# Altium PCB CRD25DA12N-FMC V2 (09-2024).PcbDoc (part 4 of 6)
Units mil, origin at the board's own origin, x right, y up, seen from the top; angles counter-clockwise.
Board outline 8000 x 8000 mil, 6 copper layers (Top Layer, Layer 2, Layer 3, Layer 4, Layer 5, Bottom Layer), stack 91 mil thick; 602 components, 333 nets, 1670 pads, 639 vias.
Unrouted connection lines stored in the file: 1.
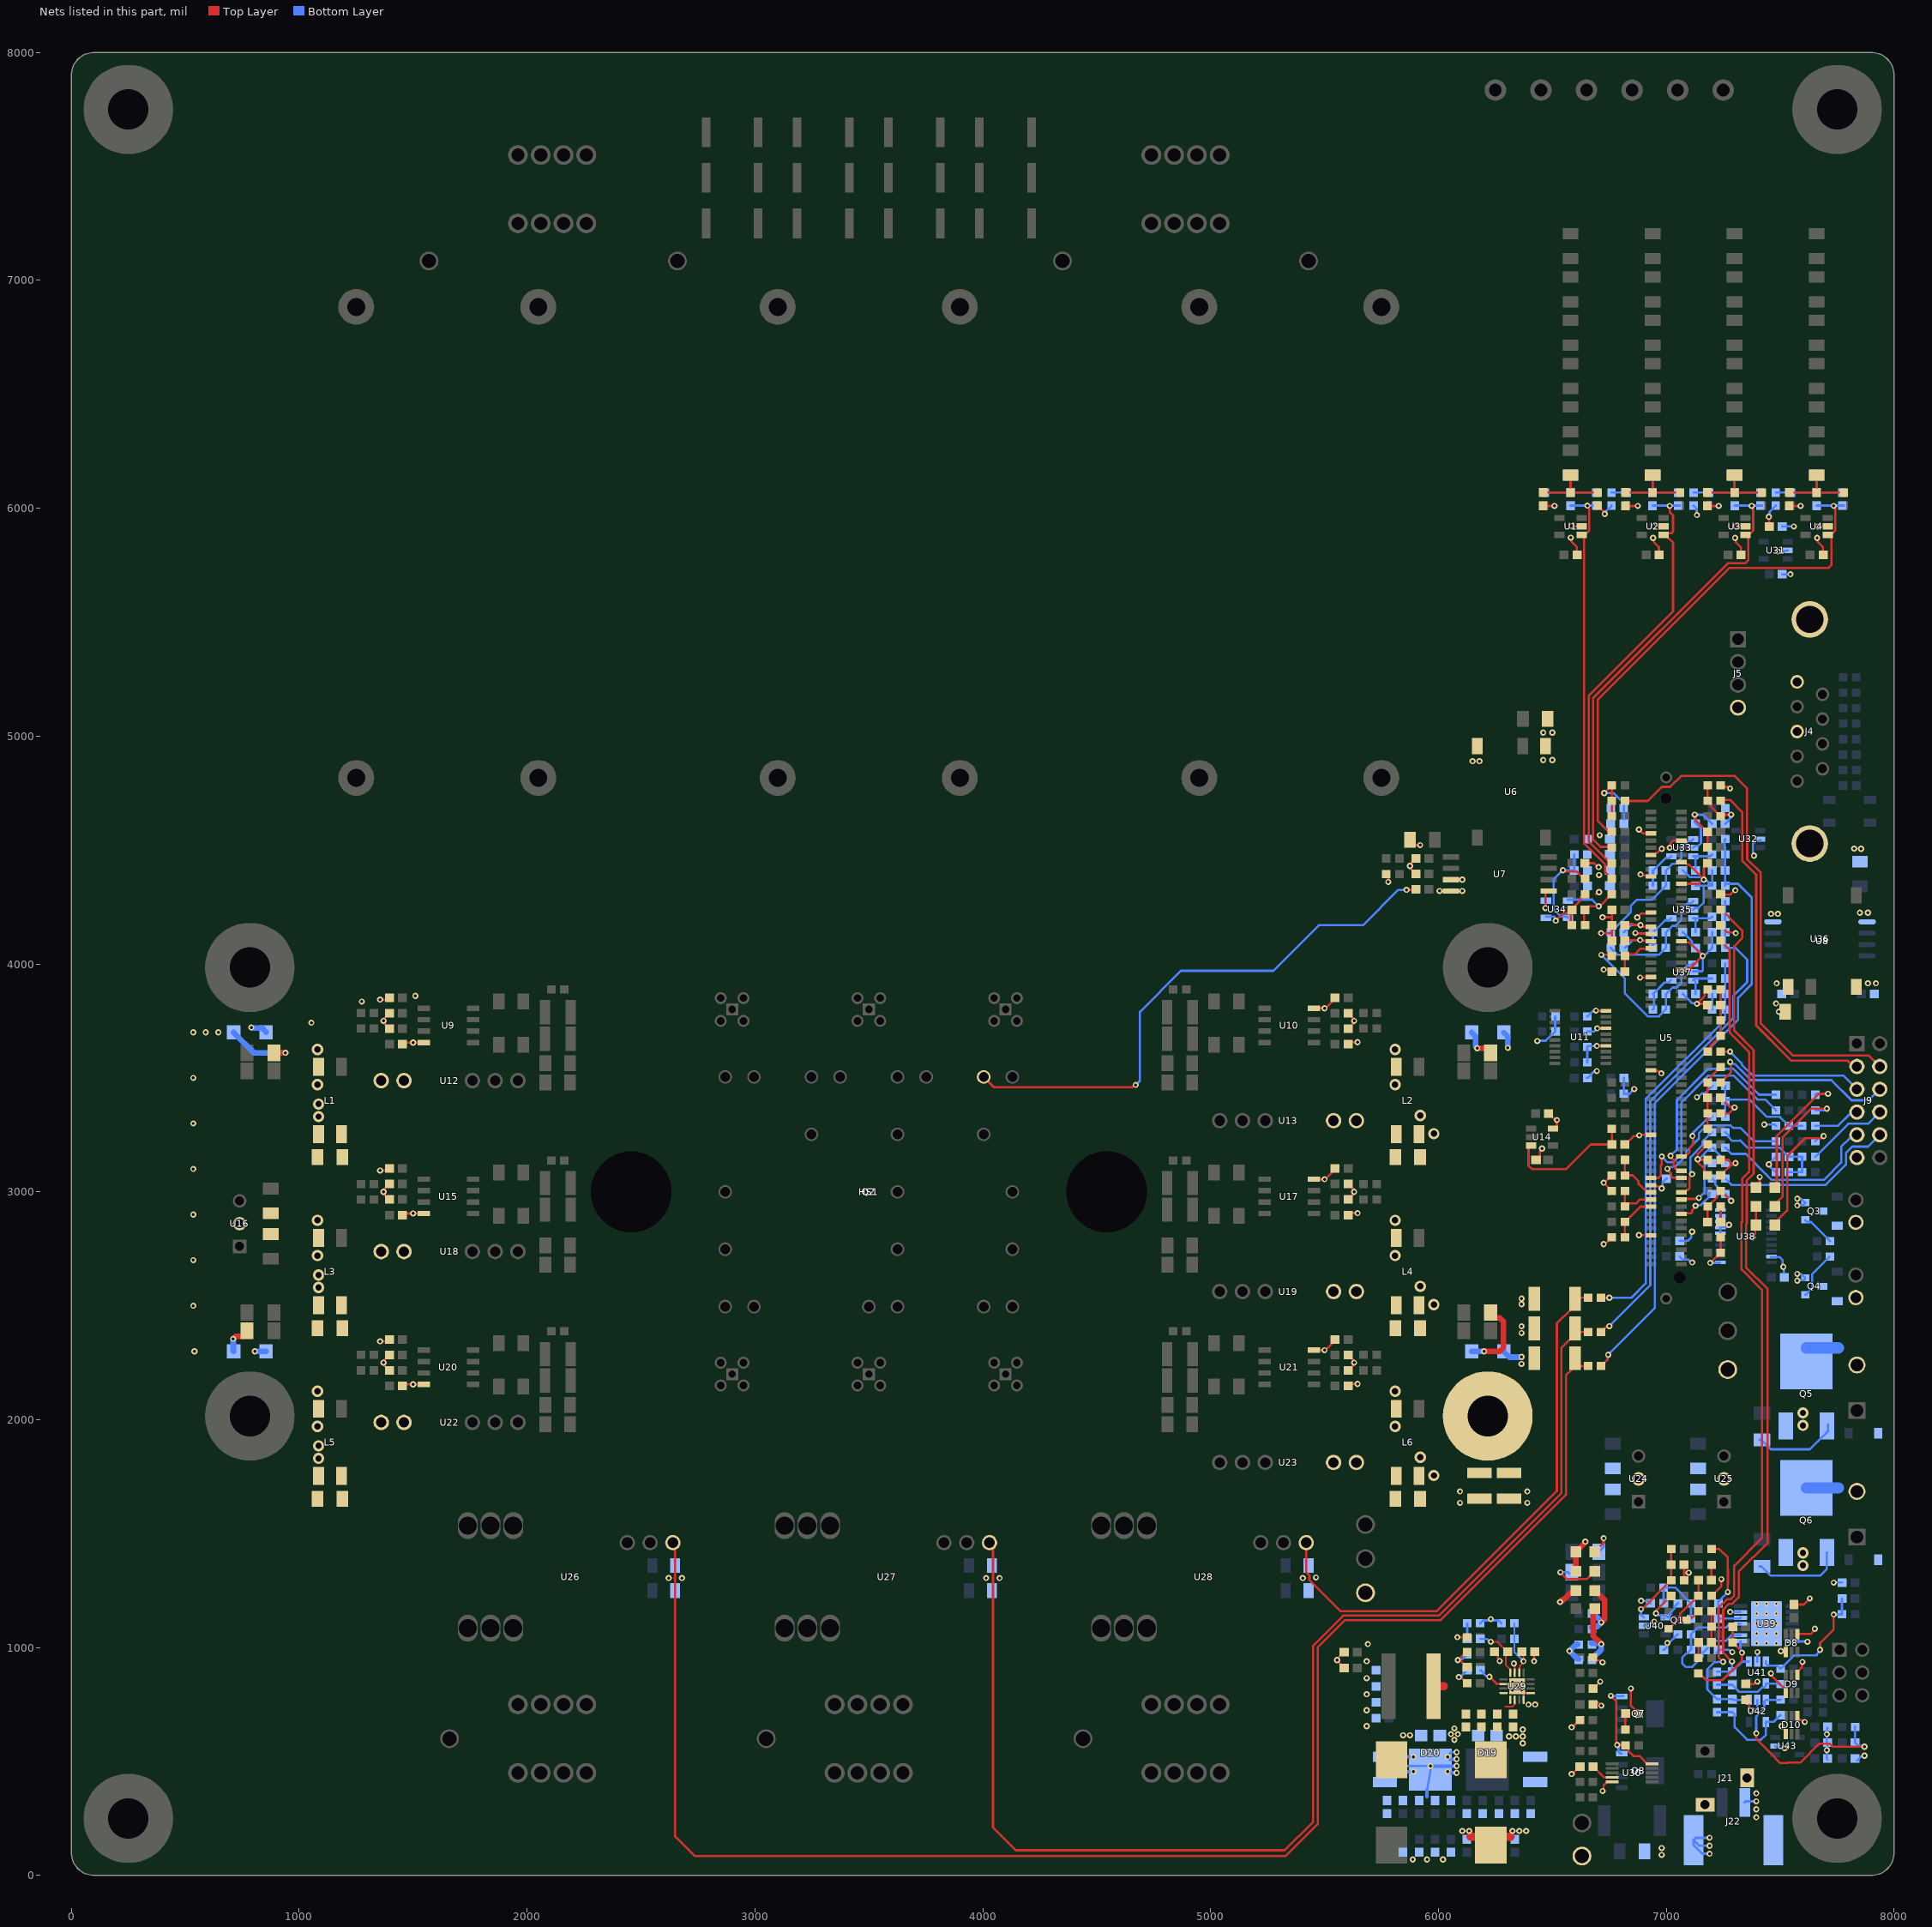
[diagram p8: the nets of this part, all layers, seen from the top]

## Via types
v1: diameter 27, hole 13, Top Layer to Bottom Layer, tented both sides, 543 vias
v2: diameter 50, hole 28, Top Layer to Bottom Layer, tented both sides, 76 vias
v3: diameter 19.68, hole 7.87, Top Layer to Bottom Layer, tented top, 15 vias
v4: diameter 19.68, hole 7.87, Top Layer to Bottom Layer, tented both sides, 5 vias

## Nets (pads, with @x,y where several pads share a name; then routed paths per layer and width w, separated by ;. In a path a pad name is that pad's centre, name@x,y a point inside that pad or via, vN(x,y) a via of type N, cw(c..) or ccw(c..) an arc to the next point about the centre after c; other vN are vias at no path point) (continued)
GND: C1.2 C2.2 C3.2 C4.2 C5.2 C6.2 C7.2 C8.2 C9.2 C10.2 C11.2 C13.2 C15.2 C16.2 C19.2 C21.2 C22.2 C23.2 C24.2 C25.2 C26.2 C27.2 C30.2 C31.2 C32.2 C33.2 C34.2 C35.2 C38.2 C39.2 C44.2 C45.2 C46.2 C49.2 C50.2 C53.2 C54.2 C55.2 C56.2 C57.2 C58.2 C61.2 C62.2 C63.2 C64.2 C71.2 C72.2 C75.2 C76.2 C77.2 C78.2 C81.2 C82.2 C89.2 C92.2 C95.2 C96.2 C97.2 C99.2 C100.2 C101.2 C102.2 C103.2 C104.2 C109.2 C117.2 C118.2 C122.2 C123.2 C124.2 C125.2 C126.2 C127.2 C129.2 C130.2 C131.2 C133.1 C134.2 C135.2 C136.2 C137.2 C138.2 C140.2 C142.2 C143.2 C144.2 C146.2 C147.2 C148.2 C149.2 C150.2 C151.2 C152.2 C153.2 C154.2 C155.2 C156.2 C157.2 C158.2 C159.2 C160.2 C161.2 C162.1 C163.1 C164.1 C166.2 C169.2 C170.2 C171.2 C172.2 C175.2 C178.2 C179.2 C180.2 C182.2 C183.2 C184.2 C186.2 C187.2 C188.2 C189.2 C190.2 C191.2 C192.2 C193.2 C194.2 C195.2 C196.2 C197.2 C198.2 C199.2 C200.2 C201.2 C202.2 C203.2 D1.1 D2.1 D3.1 D4.1 D5.1 D6.1 D8.1 D8.4 D9.1 D9.4 D10.1 D10.4 D11.1 D12.1 D15.1 D16.1 D20.1 J9.11 J21.2 J21.3 J22.1 J22.3 J22.4 L1.2 L2.2 L3.2 L4.2 L5.2 L6.2 L9.1 Q3.2 Q4.2 Q5.3 Q6.3 R38.1 R46.1 R66.1 R87.1 R91.2 R93.1 R96.1 R101.1 R108.1 R110.1 R111.1 R112.1 R113.1 R117.1 R125.1 R133.1 R134.1 R138.1 R139.1 R142.1 R145.1 R149.1 R150.1 R183.1 R186.1 R189.1 R198.1 R201.2 R202.1 R207.1 R212.1 R214.1 R215.1 R216.1 R217.1 R218.1 R219.1 R220.1 R228.1 R236.1 R254.1 R255.1 R258.1 R260.1 R263.1 TP7.1 TP10.1 TP15.1 U1.2 U2.2 U3.2 U4.2 U5.7 U5.10 U5.13 U5.16 U5.19 U5.22 U5.29 U5.35 U5.38 U5.46 U5.47 U5.65 U5.83 U5.97 U5.111 U6.1 U7.5 U8.1 U9.4 U10.4 U11.4 U11.7 U11.10 U14.5 U15.4 U16.2 U17.4 U20.4 U21.4 U24.2 U25.2 U29.1 U29.7 U29.16 U29.17 U30.5 U31.2 U32.2 U33.2 U34.5 U35.2 U36.4 U37.2 U38.1 U38.6 U38.7 U38.8 U38.9 U38.10 U38.19 U39.6 U39.14 U39.15 U40.2 U41.2 U42.2 U43.2 | length 13145.5
  Top Layer w8: v1(6331.08,930) 6331.08,924.86 6335.16,920.78 6335.16,889.81 U29.7@6334.87,889.52 ; v1(6720.98,370.5) 6724.62,374.14 6724.62,394.48 U30.5@6739.86,409.72 ; U30.5@6740.77,410.63 U30.5@6762.91,410.63
  Top Layer w10: v1(1355,2343.5) 1382.92,2343.5 C71.2@1391.42,2352 ; v1(1355,3093.5) 1382.92,3093.5 C49.2@1391.42,3102 ; v1(1355,3843.5) 1382.92,3843.5 C26.2@1391.42,3852 ; C77.2@1391.42,2216 1391.42,2220.05 1373.25,2238.22 1373.25,2246.75 v1(1370,2250) 1373.25,2253.25 1373.25,2261.78 1391.42,2279.95 C75.2@1391.42,2284 ; C57.2@1391.42,2966 1391.42,2970.05 1373.25,2988.22 1373.25,2996.75 v1(1370,3000) 1373.25,3003.25 1373.25,3011.78 1391.42,3029.95 C54.2@1391.42,3034 ; C34.2@1391.42,3716 1391.42,3720.05 1373.25,3738.22 1373.25,3746.75 v1(1370,3750) 1373.25,3753.25 1373.25,3761.78 1391.42,3779.95 C32.2@1391.42,3784 ; C81.2@1448.58,2148 1455.58,2155 v1(1500,2155) U20.4@1546.73,2155 ; C61.2@1448.58,2898 1455.58,2905 v1(1500,2905) U15.4@1546.73,2905 ; C38.2@1448.58,3648 1455.58,3655 v1(1500,3655) U9.4@1546.73,3655 ; U21.4@5453.27,2305 v1(5500,2305) 5505,2305 5505,2306.53 5550.47,2352 C72.2@5551.42,2352 ; U17.4@5453.27,3055 v1(5500,3055) 5505,3055 5505,3056.53 5550.47,3102 C50.2@5551.42,3102 ; U10.4@5453.27,3805 v1(5500,3805) 5505,3805 5505,3806.53 5550.47,3852 C27.2@5551.42,3852 ; C99.2@5586.42,900 5586.42,912.05 5555,943.47 5555,949.53 5575.47,970 C97.2@5586.42,970 ; C82.2@5608.58,2148 5617.08,2156.5 v1(5645,2156.5) ; C78.2@5608.58,2216 5608.58,2220.05 5626.75,2238.22 5626.75,2246.75 v1(5630,2250) 5626.75,2253.25 5626.75,2261.78 5608.58,2279.95 C76.2@5608.58,2284 ; C62.2@5608.58,2898 5617.08,2906.5 v1(5645,2906.5) ; C58.2@5608.58,2966 5608.58,2970.05 5626.75,2988.22 5626.75,2996.75 v1(5630,3000) 5626.75,3003.25 5626.75,3011.78 5608.58,3029.95 C55.2@5608.58,3034 ; C39.2@5608.58,3648 5617.08,3656.5 v1(5645,3656.5) ; C35.2@5608.58,3716 5608.58,3720.05 5626.75,3738.22 5626.75,3746.75 v1(5630,3750) 5626.75,3753.25 5626.75,3761.78 5608.58,3779.95 C33.2@5608.58,3784 ; v1(6083.11,1045) R142.1@6126.38,1045 ; v1@6102.73,866.75 6125.47,844 R149.1@6126.38,844 ; v1(6135,195) 6135,175.86 6140.86,170 ; L9.1@6192.99,170 L9.1@6230,132.99 L9.1@6267.01,170 ; C95.2@6246.42,981 6247.37,981 6261.24,967.14 6261.24,952.5 6268.91,944.82 v1(6268.91,940.28) ; 6317.98,170 6323.84,175.86 6323.84,193.84 v1(6325,195) ; v1(6331.08,930) 6334.33,926.75 6334.33,921.07 v1@6334.87,920.53 ; v4(6365,810) U29.17@6374.53,800.47 ; U29.16@6374.53,770.77 U29.17@6374.53,800.47 ; U29.1@6404.23,800.47 U29.17@6374.53,800.47 ; v1(6420,940) 6420,977.42 C96.2@6423.58,981 ; R91.2@6428.38,3140 6431.29,3140 6445.16,3153.86 6445.16,3175.56 6455,3185.4 v1(6455,3190) ; C1.2@6460,6011.42 6461.42,6010 v1(6509.46,6010) ; v1(6470,4245) 6470,4313.19 6476.81,4320 6488.54,4320 U7.5@6495.35,4313.19 ; C45.2@6483.58,3344 6484.53,3344 6510.27,3318.25 6516.75,3318.25 v1(6520,3315) 6520,3288.18 6511.22,3279.4 U14.5@6503.23,3279.4 ; v1(6580.67,5871.13) 6583.92,5867.88 6583.92,5853.71 6607.63,5830 6607.63,5795.95 C6.2@6608.58,5795 ; v1(6583.58,5921.42) 6584.29,5920.71 6627.52,5920.71 U1.2@6628.23,5920 ; v1(6585,445) 6587.47,445 6620.47,478 C109.2@6621.42,478 ; v1(6585,650) 6588.47,650 6618.47,680 R150.1@6625,680 ; C15.2@6638.58,4442 6683.4,4442 6700.4,4425 v1(6703.02,4425) ; C103.2@6678.58,750 6685.82,757.24 6700.74,757.24 ; C101.2@6678.58,819 6679.53,819 6710,849.47 v1(6710,850) ; R145.1@6678.62,956 6691.58,943.04 6707.36,943.04 6715.4,935 v1(6720,935) ; 6691.4,4306 6700.4,4315 v1(6705,4315) ; v1(6691.5,3795) 6691.93,3794.57 6734.57,3794.57 U11.10@6735,3794.13 ; v1(6695,3640) 6695.3,3640.3 6734.7,3640.3 U11.4@6735,3640.59 ; v1(6697.19,3717.36) U11.7@6735,3717.36 ; R38.1@6700,6011.38 6700,6010.47 v1@6726.75,5983.73 ; 6701.75,758.25 v1(6715,745) ; v1(6714.02,4135) 6761.42,4135 ; v1(6720,4205) 6761.42,4205 ; v1(6725,2770) 6728.25,2773.25 6733.73,2773.25 6760.47,2800 R110.1@6761.38,2800 ; v1(6725,3975) 6760.42,3975 C25.2@6761.42,3974 ; U30.5@6739.86,409.72 U30.5@6740.77,410.63 ; R101.1@6761.38,3004 6760.47,3004 6725,3039.47 v1(6725,3040) 6728.47,3040 6760.47,3072 R96.1@6761.38,3072 ; C24.2@6761.42,4110 6761.42,4135 ; C21.2@6761.42,4240 C21.2@6761.42,4238 6761.42,4205 ; C46.2@6818.58,3208 6819.53,3208 6855.79,3244.26 6878.25,3244.26 v1(6881.5,3247.52) 6883.89,3249.9 6932.97,3249.9 U5.83@6933.07,3249.8 ; C2.2@6820,6011.42 6821.42,6010 v1(6875,6010) ; v1(6845,820) 6845,743.58 6863.76,724.81 6863.76,723.86 6877.63,710 C104.2@6878.58,710 ; v1(6864.55,4135.68) 6866.54,4133.69 6931.08,4133.69 U5.35@6933.07,4131.69 ; v1(6872.9,4204.39) 6874,4204.39 6890.94,4221.34 6928.23,4221.34 U5.29@6933.07,4226.18 ; v1(6880,2810) 6880.57,2809.43 6929.43,2809.43 U5.111@6930,2810 ; v1(6880,4590) 6897.36,4572.64 U5.7@6933.07,4572.64 ; v1(6885,3940) 6885.47,3940.47 6934.53,3940.47 U5.47@6935,3940.94 ; v1(6887.16,4392.84) 6891.76,4392.84 6896.1,4388.5 6928.23,4388.5 U5.19@6933.07,4383.66 ; U5.13@6914.65,4482.8 6951.5,4482.8 6957.5,4488.8 6961.25,4488.8 6977.45,4505 v1(6980.19,4505) ; U5.97@6928.23,3034.17 U5.97@6933.07,3029.33 6937.91,3024.49 6965.91,3024.49 6975.4,3015 v1(6980,3015) ; U5.65@6935,3531.5 6936.04,3530.46 6964.94,3530.46 6975.4,3520 v1(6978.82,3520) ; v1(6942.09,5869.71) 6945.34,5866.45 6945.34,5852.28 6967.63,5830 6967.63,5795.95 C7.2@6968.58,5795 ; v1(6945,5920) U2.2@6988.23,5920 ; v1(7015,4510) 7018.25,4513.25 7018.25,4528.25 7031.14,4541.14 U5.10@7066.93,4541.14 ; U5.46@7066.93,3974.21 7071.77,3979.06 7104.06,3979.06 v1(7160,4035) 7099.65,4095.35 7071.77,4095.35 U5.38@7066.93,4100.2 ; U5.22@7066.93,4352.17 7142.57,4352.17 7160.4,4370 v1(7165,4370) ; U5.16@7071.77,4451.5 U5.16@7066.93,4446.65 7080.71,4446.65 7091.36,4436 7099,4436 v1(7165,4370) ; R138.1@7078.62,1295 R138.1@7078.62,1295 7078.58,1330 ; C89.2@7078.58,1363 7078.58,1330 ; C89.2@7079.53,1347.25 C89.2@7079.53,1363 ; v1(7098.39,1328.39) 7080.19,1328.39 cw(c7080.19,1330) 7078.58,1330 ; v1(7125,4655) 7128.25,4651.75 7128.25,4632.22 7180.47,4580 C11.2@7181.42,4580 C13.2@7181.42,4511 ; C3.2@7180,6011.42 7181.42,6010 v1(7230,6010) ; C30.2@7181.42,3820 7176.42,3825 v1(7135,3825) 7167.52,3857.52 7167.52,3875.04 7180.47,3888 R66.1@7181.38,3888 ; C16.2@7181.42,4442 7180.47,4442 7166.61,4428.14 7166.61,4427.19 7165,4425.58 v1(7165,4370) ; v1(7193.1,2688.1) 7193.82,2688.1 7237.72,2732 R112.1@7238.62,2732 R111.1@7238.62,2800 ; R139.1@7198.62,1227 7199.53,1227 7241.89,1269.36 v1(7241.89,1300) ; C63.2@7238.58,2868 C63.2@7238.58,2868 R108.1@7238.62,2936 ; C53.2@7238.58,3072 7239.53,3072 7253.39,3085.86 7253.39,3086.71 7284.8,3118.12 7296.33,3118.12 v1(7304.07,3125.86) ; R93.1@7238.62,3140 7270.98,3140 7292.87,3118.12 ; R87.1@7238.62,3344 7274,3344 v1(7300,3370) 7296.75,3373.25 7278.27,3373.25 7239.53,3412 C44.2@7238.58,3412 ; C23.2@7238.58,4168 7239.53,4168 7269.27,4138.25 7301.75,4138.25 v1(7305,4135) ; C19.2@7238.58,4304 7281.99,4304 7301.26,4323.27 v1(7303.03,4323.27) ; R46.1@7238.62,4790 7251.58,4777.04 7268.36,4777.04 7275.4,4770 v1(7280,4770) ; C63.2@7239.6,2869.02 7239.6,2868.79 7253.39,2855 v1(7275.54,2855) ; v1(7302.09,5869.71) 7305.34,5866.45 7305.34,5852.28 7327.63,5830 7327.63,5795.95 C8.2@7328.58,5795 ; v1(7305,5920) U3.2@7348.23,5920 ; C102.2@7348.58,771 7349.53,771 7363.39,757.14 7363.39,735.07 7370,728.46 v1(7370,723.86) ; C100.2@7348.58,840 7385.52,840 7395.52,850 v1(7400.12,850) ; v1(7378.5,2800) 7378.5,2803.88 7390,2815.38 7390,2850.34 D3.1@7393.66,2854 D2.1@7393.66,2936 ; D1.1@7387.66,3012 7410,3034.34 v1(7410,3065) ; v1(7450,5962.36) 7451.14,5961.23 C5.2@7451.14,5920 ; v1(7459.15,886.52) 7462.41,883.26 7462.41,876.41 7524.41,814.41 D9.1@7524.41,800.63 ; v1(7502.68,984.44) 7520.6,984.44 D8.1@7524.41,980.63 ; v1(7506,655.26) 7506,652.82 7520.55,638.27 D10.1@7520.55,625 ; C4.2@7540,6011.42 7541.42,6010 v1(7589.46,6010) ; C92.2@7560,1188.58 7603.58,1188.58 v1(7630,1215) ; D10.4@7575.59,699.37 7575.59,685.59 7579.45,681.73 7594.67,681.73 7603.29,673.11 v1(7607.89,673.11) ; D9.4@7575.59,879.37 7575.59,893.15 7594.61,912.17 7594.61,933.41 v1(7597.86,936.66) ; D8.4@7575.59,1059.37 7633.25,1059.37 7652.35,1078.46 v1(7652.35,1082.35) ; v1(7662.09,5869.71) 7665.34,5866.45 7665.34,5852.28 7687.63,5830 7687.63,5795.95 C9.2@7688.58,5795 ; v1(7665,5920) U4.2@7708.23,5920 ; 6761.42,4135 C22.2@6761.42,4170 6761.42,4205
  Top Layer w25: v1(6534.01,1199.85) 6534.55,1199.85 6542,1207.3 6547.3,1207.3 6578.88,1238.88 6592.54,1238.88 D6.1@6603.66,1250 ; D5.1@6603.66,1335 D4.1@6603.66,1420 6644.62,1460.96 6644.62,1464.62 v1(6645,1465)
  Top Layer w35: 6140.86,170 L9.1@6192.99,170 ; L9.1@6267.01,170 6317.98,170
  Bottom Layer w10: 5860,480 v1(5965,480) ; D20.1@5950,376.14 D20.1@5965,464.06 ; v1(6040,455) D20.1@6045,450 ; D20.1@6050,510 v1(6040,520) 6040,525.51 6054.49,540 v1(6080,540) ; v1(6090,870) 6093.25,873.25 6098.73,873.25 6125.47,900 C171.2@6126.42,900 ; R255.1@6183.62,1106 6196.58,1118.96 6219.36,1118.96 6225.4,1125 6234.6,1125 6240.64,1118.96 6263.42,1118.96 R254.1@6276.38,1106 ; D15.1@6287.4,2298.03 D15.1@6287.4,2300 ; D11.1@6287.4,3698.03 D11.1@6287.4,3700 ; D15.1@6311.93,2273.5 D15.1@6313.9,2273.5 ; v1(6433.85,3661.83) 6434.99,3662.97 6471.31,3662.97 6511.34,3703 6512.24,3703 R215.1@6512.24,3770 ; v1(6470,4245) 6470,4280.63 U34.5@6471.77,4282.4 ; C147.2@6650,3500 C147.2@6653.58,3500 6654.53,3500 6681.27,3526.75 6691.75,3526.75 v1(6695,3530) ; R219.1@6653.62,3568 R218.1@6653.62,3636 6657.62,3640 v1(6695,3640) ; R216.1@6653.62,3703 6682.82,3703 v1(6697.19,3717.36) ; R214.1@6653.62,3770 6654.53,3770 6676.27,3791.75 6688.25,3791.75 v1(6691.5,3795) ; v1(6730,5975) 6733.25,5978.25 6733.25,5983.73 6760,6010.47 R189.1@6760,6011.38 ; C146.2@6813.62,3500.78 R220.1@6813.62,3430 6838.67,3430 v1(6859.34,3450.66) ; v1(6889.85,1205.15) 6920.27,1205.15 C166.2@6931.42,1194 ; U40.2@6901.77,1095 6910.55,1103.78 6932.8,1103.78 6942.81,1113.79 v1(6947.41,1113.79) ; v1(6980,3015) 6983.25,3018.25 6983.25,3039.83 6986.61,3043.19 6986.61,3044.14 7000.47,3058 C150.2@7001.42,3058 ; C170.2@6988.58,990 6989.53,990 7003.39,1003.86 7003.39,1012.47 7007.99,1017.07 v1@7009.28,1017.07 ; v1(7005.01,1020.32) 7006.03,1020.32 v1@7009.28,1017.07 ; R258.1@7050.47,1058 7031.87,1039.39 7031.87,1039.26 7012.92,1020.32 7012.53,1020.32 v1@7009.28,1017.07 ; C152.2@7058.58,2716 7072.44,2702.14 7097.31,2702.14 7109.45,2690 v1(7114.05,2690) ; C151.2@7058.58,2785 7094.69,2785 7110.04,2800.35 7110.04,2821.35 v1(7113.3,2824.61) ; C144.2@7071.42,3868 7072.37,3868 7112.12,3828.25 7131.75,3828.25 v1(7135,3825) 7166,3825 7175.02,3834.02 7201.42,3834.02 ; C138.2@7071.42,4139 7072.37,4139 7113.76,4097.61 7113.76,4083.86 7127.63,4070 C140.2@7128.58,4070 7129.53,4070 v1@7160,4039.53 ; C131.2@7071.42,4411 7072.37,4411 7102.24,4381.14 7150.33,4381.14 7161.47,4370 v1(7165,4370) 7168.25,4366.75 7176.73,4366.75 R202.1@7200.47,4343 ; U37.2@7118.23,3967 7119.23,3968.01 7156.78,3968.01 7160,3971.22 v1(7160,4035) 7163.25,4038.25 7168.73,4038.25 7200.47,4070 R207.1@7201.38,4070 C137.2@7201.42,4139 C137.2@7201.42,4139 ; U35.2@7118.23,4238 7127.01,4246.78 7141.58,4246.78 7164.52,4269.72 7164.52,4343 ; U33.2@7118.23,4510 7127.01,4518.78 7141.58,4518.78 7151.87,4529.07 7151.87,4594.66 C123.2@7129.53,4617 ; R186.1@7120,6011.38 7132.96,5998.42 7132.96,5972.04 v1(7135,5970) ; C135.2@7128.58,4343 7164.52,4343 ; C123.2@7128.58,4617 C123.2@7129.53,4617 ; v1(7135,3415) 7139.6,3415 7156.2,3431.6 7168.5,3431.6 7201.9,3465 C148.2@7202.85,3465 ; v1(7190,95) 7158.11,95 7119.8,133.31 J22.4@7119.8,155 ; v1(7190,130) 7144.8,130 J22.4@7119.8,155 ; v1(7190,165) 7129.8,165 J22.4@7119.8,155 ; v1(7193.1,2688.1) 7193.46,2688.46 7234.64,2688.46 U38.1@7235,2688.82 ; R212.1@7201.38,3800 R212.1@7201.38,3800 7201.42,3834.02 ; C143.2@7201.42,3868 7201.42,3834.02 ; C130.2@7201.42,4411 C130.2@7201.42,4411 R202.1@7201.38,4343 R202.1@7200.47,4343 ; C122.2@7201.42,4615 7200.47,4615 7160.47,4655 v1(7125,4655) 7125,4621.53 C123.2@7129.53,4617 ; C169.2@7220.28,975.24 C169.2@7230.05,985 ; C169.2@7228.58,990 7275.4,990 7285.4,980 v1(7290,980) ; U38.6@7237.8,2817.8 U38.7@7237.8,2840.51 ; U38.7@7237.8,2843.39 U38.7@7237.8,2851.18 ; U38.8@7237.8,2866.1 U38.7@7237.8,2851.18 ; U38.8@7237.8,2868.98 U38.9@7237.8,2894.57 U38.10@7237.8,2920.16 ; v1(7275.54,2855) 7275.38,2855 7266.48,2846.1 7243.39,2846.1 U38.7@7237.8,2840.51 ; v1(7280.29,1156.3) 7280.35,1156.24 U39.6@7325.83,1156.18 U39.6@7325.83,1156.18 ; J22.1@7344.21,320.35 7348.86,325 v1(7395,325) ; v1(7370,723.86) 7373.25,727.11 7389.98,727.11 7400,737.14 U42.2@7400,770 ; v1(7385,4475) 7385,4479.6 7380.5,4484.1 7380.5,4526.97 7387.57,4534.04 7389.34,4534.04 7396.5,4541.19 7412.42,4541.19 U32.2@7414.84,4543.61 ; U41.2@7400,938.23 v1(7400,980) ; v1(7430,3295) 7476.38,3295 R228.1@7481.38,3290 ; v1(7450,5962.36) 7453.25,5965.62 7453.25,5983.73 7480,6010.47 R183.1@7480,6011.38 ; U38.19@7459.41,2714.41 7495.59,2714.41 7510.88,2699.12 7510.88,2673.19 v1(7513.45,2670.62) 7516.7,2667.37 7516.7,2646.84 7518.54,2645 ; U43.2@7478.7,567.6 7485.51,560.79 7509.61,560.79 7509.77,560.62 7517.87,560.62 v1(7520,558.49) ; R236.1@7481.38,3086 7480.47,3086 7450,3116.47 v1(7450,3120) 7450,3123.53 7480.47,3154 C149.2@7481.42,3154 ; v1(7490,5810) 7492.5,5812.5 7530.65,5812.5 U31.2@7533.15,5815 ; C118.2@7508.58,5710 v1(7545,5710) ; C117.2@7508.58,5920 v1(7560,5920) ; U39.14@7554.17,1028.23 7555.63,1026.77 7618.55,1026.77 v1(7620,1025.32) ; v1(7575,2610) 7576.65,2611.65 7602.91,2611.65 7608.66,2617.4 7608.66,2622.4 7592.56,2638.5 7576.5,2638.5 v1(7575,2640) ; v1(7575,2940) 7576.65,2941.65 7599.88,2941.65 7607.15,2948.92 7607.15,2953.92 7592.56,2968.5 ; v1(7575,2970) 7576.5,2968.5 v1@7587.56,2968.5 ; Q3.2@7601.26,2940 7601.26,2943.03 Q3.2@7610.63,2952.4 ; Q3.2@7608.66,2952.4 7592.56,2968.5 ; v1(7705,550) 7705,511.58 C184.2@7708.58,508 ; v1(7705,620) 7705,581.58 7708.58,578 v1@7708.58,550 ; v1@7706.69,620 7706.69,645.11 C180.2@7708.58,647 ; v1(7735,1285) C161.2@7771.42,1285 ; C183.2@7838.53,504 7856.27,521.75 7866.75,521.75 v1(7870,525) ; 7164.52,4343 R202.1@7200.47,4343 ; U38.7@7237.8,2840.51 7237.69,2840.62 7237.69,2851.07 U38.7@7237.8,2851.18 ; v1@7587.56,2968.5 7592.56,2968.5 ; v1@7587.56,2968.5 7592.56,2968.5
  Bottom Layer w15: 5855,520 v1(5890,520) ; 5860,455 v1(5890,455) ; 5950,345 D20.1@5950,376.14 ; v1(5965,480) v1(6080,480) ; D20.1@6045,450 v1(6080,450) ; D20.1@6050,510 v1(6080,510)
  Bottom Layer w25: v1(790,3721.08) 790.54,3721.08 792.62,3719 837.3,3719 854.33,3701.97 D12.1@854.33,3700 ; v1(805,2300) D16.1@854.33,2300 ; D15.1@6287.4,2298.03 D15.1@6311.93,2273.5 ; D11.1@6287.4,3698.03 6304.43,3681 6304.43,3632.61 6305,3632.04 v1(6305,3631.5) ; D15.1@6313.9,2273.5 6315.01,2274.62 6364.62,2274.62 v1(6365,2275) ; R260.1@6610,1013.53 6603.53,1013.53 v1(6575,985) 6575.47,985 6610.47,950 R263.1@6616.47,950
  other v1: 5887.4,70 5950,70 6020,70 6980,90 6980,120 6105,195 6355,195 6385,195 7395,255 7395,290 7395,360 5685,655 5685,725 6395,750 6425,750 5685,795 5685,865 5685,940 5555,945 5690,1014.94 6230,1125 2621.5,1305 2680,1305 4015,1305 4073.5,1305 5405,1305 5462.65,1307.65 6095,1635 6390,1635 6095,1685 6390,1685 6364.7,2244.7 540,2300 6365,2380 6364.85,2409.85 535,2500 6365,2506.5 6365,2531.5 535,2700 535,2900 535,3100 535,3300 535,3500 535,3700 590,3700 645,3700 1053.21,3741.79 7494.21,3790 7481.72,3826.72 1275,3835 1510,3860 7485,3915 7460,4220 7490,4220 6705,4390 6707.89,4565 6460,4895 6500,4895 6460,5015 6500,5015
  other v2: 7600,1360 7600,1415 1080,1970 5810,1970 7600,1974.76 7600,2029.76 1080,2125 5810,2125 1080,2720 5810,2720 1080,2875 5810,2875 1080,3470 5810,3470 1080,3625 5810,3625
  other v3: 7396.69,1018.39 7440,1018.39 7483.31,1018.39 7396.69,1061.69 7440,1061.69 7483.31,1061.69 7396.69,1105 7440,1105 7483.31,1105 7396.69,1148.31 7440,1148.31 7483.31,1148.31 7396.69,1191.61 7440,1191.61 7483.31,1191.61
  other v4: 6325,810 6345,830 6325,850 6365,850
GND_ISO: C128.2 C141.2 J4.3 J4.5 J4.10 J4.11 J5.4 U8.4 U36.5
  other v1: 7885,3915 7920,3915 7850,4225 7885,4225 7855,4505 7824.6,4506.19
GND_NTC: C12.2 C14.2 C17.2 C18.2 Q2.NTC1 R55.1 U6.4 U7.3 U7.4 | length 2775.8
  Top Layer w10: Q2.NTC1@4003.94,3503.94 4048.94,3458.94 4657.16,3458.94 4667.01,3468.79 v1(4671.61,3468.79) ; R55.1@5771.38,4395 5780,4386.38 v1(5780,4360) ; v1(5860,4325) 5898.47,4325 5900.47,4327 C18.2@5901.42,4327 ; v1(5875,4430) 5878.25,4426.75 5878.25,4417.22 5900.47,4395 C17.2@5901.42,4395 ; C12.2@5875.81,4545 5875.81,4542.06 5896.51,4521.36 v1(5920,4521.36) ; v1@5878.25,4440.78 5900.47,4463 C14.2@5901.42,4463 ; v1(6005,4320) U7.4@6055.43,4320 v1(6105,4320) ; U7.3@6055.43,4370 v1(6105,4370)
  Bottom Layer w10: v1(4671.61,3468.79) 4690,3487.18 4690,3790 4870,3970 5275,3970 5475,4170 5668.28,4170 5823.28,4325 v1(5860,4325)
  other v1: 6150,4890 6180,4890
GPIO35: R226.2 U5.90 | length 251.1
  Top Layer w10: U5.90@7066.93,3155.31 7080.71,3155.31 7091.36,3165.97 7095.11,3165.97 7101.55,3172.41 7101.55,3191.33 7118.62,3208.4 7118.62,3216.78 7118.25,3217.15 7118.25,3241.75 v1(7115,3245)
  Bottom Layer w10: v1(7115,3245) 7118.25,3248.25 7118.25,3259.53 7175.77,3317.04 7188.42,3317.04 R226.2@7201.38,3330
GPIO54: R229.2 U5.100 | length 336.4
  Top Layer w10: U5.100@7066.93,2997.83 7080.71,2997.83 7091.36,3008.49 7095.11,3008.49 7101.55,3014.93 7101.55,3061.95 7113.49,3073.89 v1(7113.49,3077.37)
  Bottom Layer w10: v1(7113.49,3077.37) 7113.49,3081.97 7106.5,3088.96 7106.5,3151.81 7158.09,3203.39 7158.09,3219.5 7163.5,3224.91 7163.5,3225.03 7200.47,3262 R229.2@7201.38,3262
GPIO55: R234.2 U5.102 | length 253.4
  Top Layer w10: U5.102@7066.93,2966.34 7069.09,2968.5 7128.29,2968.5 7129.16,2969.37 7139.98,2969.37 v1(7143.23,2972.62)
  Bottom Layer w10: v1(7143.23,2972.62) 7167.73,2997.12 7167.73,3055.16 7167.52,3055.38 7167.52,3113.42 R234.2@7184.09,3130
GPIO57: R238.2 U5.106 | length 177.9
  Top Layer w10: U5.106@7066.93,2903.35 7068.73,2905.15 7107.81,2905.15 7113.67,2911.01 7113.67,2919.32 7128.45,2934.1 v1(7128.45,2938.7)
  Bottom Layer w10: v1(7128.45,2938.7) 7131.7,2941.95 7152.87,2941.95 7171.73,2960.81 7171.73,2961.26 7187.52,2977.04 7187.52,2992.52 R238.2@7190,2995
ID0: R92.1 R96.2 U5.99 | length 218.9
  Top Layer w10: R92.1@6818.62,3140 R96.2@6818.62,3072 6852.48,3072 6878.69,3045.8 6878.69,3034.69 6910.7,3002.68 6925.7,3002.68 U5.99@6931.81,2996.57
ID1: R101.2 R107.1 U5.101 | length 199.4
  Top Layer w10: R101.2@6818.62,3004 R107.1@6818.62,2936 6831.58,2948.96 6867.2,2948.96 6884.58,2966.34 6928.98,2966.34 6932.87,2962.44 U5.101@6935,2964.57
ID2: R109.1 R110.2 U5.103 | length 210.1
  Top Layer w10: R110.2@6818.62,2800 R109.1@6818.62,2868 6819.53,2868 6886.37,2934.84 U5.103@6933.07,2934.84
IU: R125.2 R128.1 U26.9 | length 7014.5
  Top Layer w10: U26.9@2640,1460 2650,1450 2650,170 2735,85 5330,85 5470,225 5470,1000 5590,1120 6010,1120 6560,1670 6560,2195 6582.91,2217.91 6582.91,2235.39 R125.2@6602.52,2255 ; R125.2@6602.52,2254.61 6622.13,2235 R128.1@6656.38,2235
IU_FILT: C130.1 R128.2 R199.1 R200.1 R202.2 | length 2680.4
  Top Layer w10: R128.2@6713.62,2235 6714.53,2235 6741.75,2262.22 6741.75,2281.75 v1(6745,2285)
  Bottom Layer w10: v1(6745,2285) 6950,2490 6950,3389.85 7315,3754.85 7315,3851.72 7375,3911.72 7375,4291.6 7314.84,4351.77 7260.39,4351.77 R202.2@7258.62,4350 ; R202.2@7258.62,4343 R202.2@7258.62,4350 ; R199.1@7258.62,4548 7255.96,4545.33 7255.96,4515.04 7258.62,4512.38 R200.1@7258.62,4480 R200.1@7258.62,4480 C130.1@7258.58,4411 C130.1@7258.58,4411 R202.2@7258.62,4350
IU_MEAS: C22.1 R206.2 U5.33 | length 203.6
  Top Layer w10: C22.1@6823.7,4174.87 6853.45,4174.87 6858.16,4170.17 v1(6886.95,4170.17) ; v1@6886.74,4175 6898.71,4163.03 U5.33@6933.39,4163.03
  Bottom Layer w10: R206.2@6813.62,4139 6814.53,4139 6827.48,4151.96 6827.48,4152.86 6844.79,4170.17 v1(6886.95,4170.17)
IV: R117.2 R122.1 U27.9 | length 5685.2
  Top Layer w10: U27.9@4030,1460 4030,1444.51 4045,1429.51 4045,210 4145,110 5325,110 5450,235 5450,1008.28 5581.72,1140 5675,1140 6001.72,1140 6540,1678.28 6540,2315 6576.85,2351.85 6582.91,2351.85 6602.52,2371.46 6602.52,2385 R122.1@6656.38,2385
IV_FILT: C137.1 R122.2 R204.1 R205.1 R207.2 | length 2228.8
  Top Layer w10: R122.2@6713.62,2385 6714.53,2385 6736.27,2406.75 6746.75,2406.75 v1(6750,2410)
  Bottom Layer w10: v1(6750,2410) 6930,2590 6930,3398.14 7295,3763.14 7295,3860 7355,3920 7355,4018.81 7303.81,4070 R207.2@7258.62,4070 C137.1@7258.58,4139 C137.1@7258.58,4139 C137.1@7258.58,4139 R205.1@7258.62,4207 R204.1@7258.62,4275
IV_MEAS: C24.1 R209.2 U5.37 | length 208.3
  Top Layer w10: C24.1@6809.06,4104.85 v1(6885,4104.85) 6887.32,4102.52 6930.9,4102.52 U5.37@6934.21,4099.21
  Bottom Layer w10: R209.2@6818.62,4070 6819.53,4070 6854.37,4104.85 v1(6885,4104.85)
IW: R113.2 R114.1 U28.9 | length 2439.7
  Top Layer w10: U28.9@5420,1460 5420,1330.31 5434.15,1316.15 5434.15,1295.85 5570,1160 5993.43,1160 6520,1686.57 6520,2422.48 6579.37,2481.85 6584.37,2481.85 R113.2@6607.52,2505 ; R113.2@6607.52,2535 R114.1@6659.41,2535
IW_FILT: C143.1 R114.2 R210.1 R211.1 R212.2 | length 1771.7
  Top Layer w10: R114.2@6713.62,2535 v1(6750,2535)
  Bottom Layer w10: v1(6750,2535) 6846.72,2535 6910,2598.28 6910,3406.42 7258.62,3755.04 R212.2@7258.62,3800 R212.2@7258.62,3800 C143.1@7258.58,3868 R211.1@7258.62,3936 R211.1@7258.62,3936 R210.1@7258.62,4003
IW_MEAS: C25.1 R63.2 U5.39 | length 194.9
  Top Layer w10: C25.1@6818.58,3974 6818.58,4041.96 6818.62,4042 6861.55,4042 6886.48,4066.93 6935,4066.93 U5.39@6934.85,4066.78
LED_G: R231.2 U5.96 | length 697
  Top Layer w10: v1(7005,3101) 7005,3096.4 7021.24,3080.16 7021.24,3068.36 7028.31,3061.29 7066.46,3061.29 U5.96@7066.93,3060.83
  Bottom Layer w10: v1(7005,3101) 7009.6,3101 7018.1,3109.5 7039.5,3109.5 7086.5,3156.5 7086.5,3176.19 7143.5,3233.19 7143.5,3256.49 7177.96,3290.96 7282.04,3290.96 7292.49,3280.5 7324.5,3280.5 7383,3222 R231.2@7481.38,3222
LED_R: R222.2 U5.94 | length 890.4
  Top Layer w10: v1(7018.69,3158) 7018.69,3153.4 7032.31,3139.79 7032.31,3109.42 7038.75,3102.98 7042.5,3102.98 7053.15,3092.32 U5.94@7066.93,3092.32
  Bottom Layer w10: v1(7018.69,3158) 7046.5,3185.81 7046.5,3401.5 7185,3540 7293.43,3540 7407.43,3426 R222.2@7481.38,3426
LED_Y: R225.2 U5.95 | length 998.4
  Top Layer w10: U5.95@6933.07,3060.83 6933.48,3060.41 6966.29,3060.41 6976.5,3070.62 6976.5,3115.95 6980.19,3119.65 v1(6980.19,3155)
  Bottom Layer w10: v1(6980.19,3155) 7005.69,3129.5 7030.5,3129.5 7066.5,3165.5 7066.5,3391.5 7185,3510 7295,3510 7400,3405 7434.38,3405 R225.2@7481.38,3358
NetC1_1: C1.1 R33.2 R37.1 R38.2 | length 316.3
  Top Layer w10: C1.1@6460,6068.58 R37.1@6580,6068.62 R37.1@6580,6068.62 ; R33.2@6580,6144.88 R37.1@6580,6068.62 ; R38.2@6700,6068.62 R37.1@6580,6068.62
NetC2_1: C2.1 R34.2 R39.1 R40.1 | length 316.3
  Top Layer w10: C2.1@6820,6068.58 R39.1@6940,6068.62 R39.1@6940,6068.62 ; R34.2@6940,6144.88 R39.1@6940,6068.62 ; R40.1@7060,6068.62 R39.1@6940,6068.62
NetC3_1: C3.1 R35.2 R41.1 R42.1 | length 316.3
  Top Layer w10: C3.1@7180,6068.58 R41.1@7300,6068.62 R41.1@7300,6068.62 ; R35.2@7300,6144.88 R41.1@7300,6068.62 ; R42.1@7420,6068.62 R41.1@7300,6068.62
NetC4_1: C4.1 R36.2 R43.1 R44.1 | length 316.3
  Top Layer w10: C4.1@7540,6068.58 C4.1@7540,6068.58 R43.1@7660,6068.62 ; R36.2@7660,6144.88 R43.1@7660,6068.62 ; R44.1@7780,6068.62 R43.1@7660,6068.62
NetC20_1: C20.1 R59.1 R61.1 U34.1 | length 370
  Top Layer w10: R61.1@6638.62,4170 6638.62,4237.09 6653.39,4251.86 6658.3,4251.86 6659.25,4252.81 v1(6703.96,4252.81) v1@6699.36,4252.81 ; v1@6705.62,4251.15 6760.47,4306 R59.1@6761.38,4306
  Bottom Layer w10: U34.1@6568.23,4282.4 6674.37,4282.4 v1(6703.96,4252.81)
NetC20_2: C20.2 R58.1 R61.2 U34.4 | length 306.7
  Top Layer w10: v1(6514.85,4189.85) 6549.14,4224.14 6571.61,4224.14 6582.37,4234.9 6582.37,4238 6624.76,4280.39 6624.76,4293.04 6637.72,4306 R58.1@6638.62,4306 ; C20.2@6581.42,4238 6581.38,4237.96 6581.38,4170 R61.2@6582.28,4170
  Bottom Layer w10: U34.4@6471.77,4207.6 6507.8,4207.6 6511.59,4203.81 6511.59,4193.1 v1(6514.85,4189.85)
NetC30_1: C30.1 R66.2 R71.1 R76.1 R79.2 | length 296.8
  Top Layer w10: R79.2@7181.38,3616 7182.28,3616 7195.24,3628.96 7195.24,3641.52 7237.72,3684 R76.1@7238.62,3684 R71.1@7238.62,3752 R71.1@7238.62,3752 C30.1@7238.58,3820 C30.1@7238.58,3820 R66.2@7238.62,3888
NetC44_1: C44.1 R82.1 R84.2 R87.2 R89.1 | length 296.8
  Top Layer w10: R89.1@7181.38,3276 R87.2@7181.38,3344 R87.2@7181.38,3344 C44.1@7181.42,3412 C44.1@7181.42,3412 R84.2@7181.38,3480 7182.28,3480 7195.24,3492.96 7195.24,3505.52 7237.72,3548 R82.1@7238.62,3548
NetC46_1: C46.1 R88.2 U14.3 | length 581.3
  Top Layer w10: U14.3@6406.77,3204.6 6404.39,3204.6 6395.61,3195.82 6395.61,3114.39 6410,3100 6561.29,3100 6669.29,3208 C46.1@6761.42,3208 6761.42,3274.67 R88.2@6762.76,3276
NetC47_1: C47.1 L1.4 U12.1
NetC47_2: C47.2 L1.3 U12.2
  other v2: 1085,3330 1085,3385
NetC48_1: C48.1 L2.4 U13.1
  other v2: 5980,3255 5920,3335
NetC48_2: C48.2 L2.3 U13.2
NetC53_1: C53.1 R90.1 R93.2 R232.2 R234.1 | length 372.2
  Top Layer w10: v1@7135,3140 R93.2@7171.38,3140 ; C53.1@7180,3072.47 7166.61,3085.86 7166.61,3101.67 7140.91,3127.38 7140.91,3140.6 7138.25,3143.25 7138.25,3165.78 7180.47,3208 R90.1@7181.38,3208
  Bottom Layer w10: v1(7137.65,3142.65) 7142.25,3142.65 7157,3157.39 7157.39,3157.39 7181.04,3181.04 7187.52,3181.04 R232.2@7191.88,3185.41 ; R232.2@7201.38,3194 7202.28,3194 7215.24,3181.04 7215.24,3180.14 7244.99,3150.39 7244.99,3138.96 7257.94,3126 R234.1@7258.62,3126
NetC63_1: C63.1 R102.1 R108.2 R237.2 R238.1 | length 358.8
  Top Layer w10: C63.1@7181.42,2868 R108.2@7181.38,2936 R108.2@7181.38,2936 7182.28,2936 7224.76,2978.48 7224.76,2991.04 7237.72,3004 7239.53,3004 7283.22,2960.31 v1(7285,2960.31)
  Bottom Layer w10: R237.2@7201.38,3058 7201.61,3058 7214.56,3045.04 7214.56,3033.15 7233.32,3014.39 7257.72,2990 7259.53,2990 7285,2964.53 v1(7285,2960.31)
NetC69_1: C69.1 L3.4 U18.1
NetC69_2: C69.2 L3.3 U18.2 | length 4.1
  Top Layer w10: L3.3@1090,2502.36 L3.3@1092.89,2505.26
  other v2: 1085,2580 1085,2635
NetC70_1: C70.1 L4.4 U19.1
  other v2: 5980,2505 5920,2585
NetC70_2: C70.2 L4.3 U19.2
NetC87_1: C87.1 L5.4 U22.1
NetC87_2: C87.2 L5.3 U22.2
  other v2: 1085,1830 1085,1885
NetC88_1: C88.1 L6.4 U23.1
  other v2: 5980,1755 5920,1835
NetC88_2: C88.2 L6.3 U23.2
NetC89_1: C89.1 R135.1 R138.2 U40.3 | length 364.9
  Top Layer w10: v1(6889.16,1168.01) 6893.48,1168.01 7020.47,1295 R138.2@7021.38,1295 C89.1@7021.42,1363 C89.1@7021.42,1363 R135.1@7021.38,1432 R135.1@7021.38,1432
  Bottom Layer w10: v1(6889.16,1168.01) 6889.16,1141.18 6892.99,1141.18 U40.3@6901.77,1132.4
NetC90_1: C90.1 R137.2 | length 68
  Top Layer w10: C90.1@7198.58,1295 C90.1@7198.58,1295 R137.2@7198.62,1363
NetC90_2: C90.2 Q1.2 R139.2 | length 268.3
  Top Layer w10: Q1.2@7010.63,1082.6 7012.6,1082.6 7060.65,1130.65 7060.65,1147.18 7140.47,1227 R139.2@7141.38,1227 R139.2@7141.38,1227 C90.2@7141.42,1295
NetC91_2: C91.2 R250.1 U40.4 | length 259.2
  Top Layer w10: v1(6955,1150) 6958.25,1153.25 6958.25,1164.78 7018.42,1224.95 7018.42,1230 C91.2@7021.42,1227
  Bottom Layer w10: v1(6955,1150) 6959.6,1150 6968.42,1141.18 6998.31,1141.18 7007.09,1132.4 7015.87,1141.18 7015.87,1150.04 7037.52,1171.69 7037.52,1181.04 7050.47,1194 R250.1@7051.38,1194 ; U40.4@6983.23,1127.4 U40.4@6992.09,1127.4
NetC93_1: C93.1 R143.1 R148.1 U39.1 | length 454.3
  Top Layer w10: R148.1@7141.38,886 7154.33,873.04 7159.27,873.04 7168.76,863.56 7168.76,863.49 7175.2,857.04 7247.04,857.04 7332.39,942.39 v1(7332.39,977.67) ; C93.1@7291.42,1091 C93.1@7291.42,1091 R143.1@7291.38,1022 7292.28,1022 v1@7332.39,981.89
  Bottom Layer w10: U39.1@7325.83,1028.23 7325.83,1025.2 7325,1024.37 7325,989.66 7332.39,982.27 v1(7332.39,977.67)
NetC94_1: C94.1 R146.2 | length 68.5
  Top Layer w10: R146.2@7141.38,954 R146.2@7141.38,954 C94.1@7141.42,1022 ; C94.1@7154.92,1024.17 C94.1@7155.24,1023.86
NetC94_2: C94.2 R140.2 R141.1 | length 149.2
  Top Layer w10: R140.2@7189.73,1151.02 7197.72,1159 R140.2@7198.62,1159 R141.1@7198.62,1091 R141.1@7198.62,1091 C94.2@7198.58,1022
NetC95_1: C95.1 C168.1 U29.8 | length 246.2
  Top Layer w8: v1(6230,1025) 6258.63,1025 6302.63,981 C95.1@6303.58,981 6296.41,973.83 6296.41,922.27 6315.47,903.21 U29.8@6315.47,889.23
  Bottom Layer w8: C168.1@6183.58,1038 6213.11,1038 6226.11,1025 v1(6230,1025)
NetC96_1: C96.1 R254.2 R259.1 U29.6 | length 265.6
  Top Layer w8: 6354.84,909.23 6358.58,912.97 6358.58,920.12 6373.31,934.86 6373.31,974.11 C96.1@6366.42,981
  Bottom Layer w8: R254.2@6333.62,1106 R259.1@6333.62,1038 6333.62,979.69 v1(6373.31,940) ; v1@6370,939.47 v1@6370.91,939.47
NetC98_1: C98.1 R144.2 R262.1 | length 162.3
  Top Layer w10: C98.1@6126.42,913 6112.56,926.86 6111.61,926.86 6096.73,941.75 6088.25,941.75 v1(6085,945) 6107.04,967.04 6113.42,967.04 R144.2@6126.38,980
  Bottom Layer w10: v1(6085,945) 6088.25,948.25 6103.73,948.25 6125.47,970 R262.1@6126.38,970
NetC104_1: C104.1 R151.1 | length 71.2
  Top Layer w10: R151.1@6821.38,640 6820,641.38 6820,708.58 C104.1@6821.42,710
NetC105_1: C105.1 C106.1 C107.1 C108.1 L7.2 U29.12 U29.13 U29.14 | length 132.2
  Top Layer w8: 6025,830 6030,825 ; 6295,740 6325,740 6334.89,749.89 6334.89,770.49 U29.14@6335.16,770.77 U29.14@6335.16,757.18
  Top Layer w35: L7.2@5978.43,830 6025,830
NetC105_2: C105.2 C106.2 D20.2 D20.3 L8.1 R274.1
  other v1: 6070,595 5845,615 5875,615 6055,620 6085,620 6070,645
NetC107_2: C107.2 C108.2 D19.2 D19.3 L9.2 R273.1
  other v1: 6370,580 6310,610 6340,610 6370,610 6370,640
NetC109_1: C109.1 U30.4 | length 104.2
  Top Layer w8: C109.1@6678.58,478 6726.58,430 U30.4@6762.91,430
NetC113_1: C113.1 R177.2 R181.2 R182.1 R183.2 | length 376.3
  Bottom Layer w10: R183.2@7480,6068.62 R182.1@7548,6068.62 C113.1@7660,6068.58 ; R177.2@7660,6144.88 C113.1@7660,6068.58 ; R181.2@7780,6068.62 C113.1@7660,6068.58
NetC113_2: C113.2 R51.1 R181.1 U4.1 | length 2298
  Top Layer w10: R51.1@6761.38,4566 6699.39,4627.99 6699.39,5159.39 7278.5,5738.5 7713.5,5738.5 7725,5750 7725,5874.61 7712.62,5886.99 7717.01,5891.38 7731.58,5891.38 7741.87,5901.66 7741.87,5998.53 7735,6005.4 v1(7735,6010)
  Bottom Layer w10: C113.2@7660,6011.42 7779.96,6011.42 R181.1@7780,6011.38
NetC114_1: C114.1 R178.2 R184.2 R185.1 R186.2 | length 376.3
  Bottom Layer w10: R186.2@7120,6068.62 R185.1@7188,6068.62 C114.1@7300,6068.58 C114.1@7300,6068.58 ; R178.2@7300,6144.88 C114.1@7300,6068.58 ; R184.2@7420,6068.62 7419.96,6068.58 C114.1@7300,6068.58
NetC114_2: C114.2 R52.1 R184.1 U3.1 | length 2033.3
  Top Layer w10: R52.1@6757.6,4513.87 6711.13,4513.87 6679.39,4545.61 6679.39,5167.67 7270.22,5758.5 7346.31,5758.5 7359.39,5771.58 7359.39,5873.82 7350.61,5882.6 U3.1@7348.23,5882.6 7357.01,5891.38 7371.58,5891.38 7381.87,5901.66 7381.87,5998.53 7375,6005.4 v1(7375,6010)
  Bottom Layer w10: C114.2@7300,6011.42 C114.2@7300,6011.42 R184.1@7420,6011.38
NetC115_1: C115.1 R179.2 R187.2 R188.1 R189.2 | length 376.3
  Bottom Layer w10: R189.2@6760,6068.62 R188.1@6828,6068.62 C115.1@6940,6068.58 C115.1@6940,6068.58 ; R179.2@6940,6144.88 C115.1@6940,6068.58 ; R187.2@7060,6068.62 C115.1@6940,6068.58 C115.1@6940,6068.58
NetC115_2: C115.2 R54.1 R187.1 U2.1 | length 1941.6
  Top Layer w10: R54.1@6761.38,4442 6748.42,4454.96 6741.76,4454.96 6659.39,4537.33 6659.39,5175.96 7030,5546.57 7030,5849.09 7005.87,5873.23 7005.87,5873.82 6992.95,5886.73 6992.36,5886.73 6996.5,5890.87 7024.13,5890.87 7029.99,5896.72 7029.99,5967.61 7016.1,5981.5 7016.1,6008.9 v1(7015,6010)
  Bottom Layer w10: C115.2@6940,6011.42 7059.96,6011.42 R187.1@7060,6011.38
NetC116_1: C116.1 R180.2 R190.1 R191.1 | length 316.3
  Bottom Layer w10: R191.1@6460,6068.62 C116.1@6580,6068.58 C116.1@6580,6068.58 ; R180.2@6580,6144.88 C116.1@6580,6068.58 ; R190.1@6700,6068.62 6699.96,6068.58 C116.1@6580,6068.58
NetC116_2: C116.2 R57.1 R190.2 U1.1 | length 1840.4
  Top Layer w10: v1(6653.58,6011.42) 6653.58,6006.82 6661.87,5998.53 6661.87,5901.66 6651.58,5891.38 6637.01,5891.38 U1.1@6628.23,5882.6 6630.61,5882.6 6639.39,5873.82 6639.39,4529.04 6731.52,4436.91 6731.52,4402.96 6760.47,4374 R57.1@6761.38,4374
  Bottom Layer w10: C116.2@6580,6011.42 v1(6653.58,6011.42) 6699.96,6011.42 R190.2@6700,6011.38
NetC122_1: C122.1 R46.2 R48.2 R50.1 R197.1 | length 262.7
  Top Layer w10: R48.2@7181.38,4720 R46.2@7181.38,4790 ; R48.2@7183.66,4718.62 7195.24,4707.04 7195.24,4691.1 7236.34,4650 7237.24,4650 7242.24,4655 v1(7285,4655)
  Bottom Layer w10: C122.1@7258.58,4615 7259.53,4615 7273.39,4628.86 7273.39,4632.52 7281.75,4640.87 7281.75,4651.75 v1(7285,4655)
NetC124_1: C124.1 R45.1 R47.2 R49.1 R198.2 | length 357.2
  Top Layer w10: v1(6727.89,4750) 6727.89,4751.42 6748.72,4772.24 6760,4772.24 6757.76,4770 6761.38,4766.38 6761.38,4700 R49.1@6761.38,4634
  Bottom Layer w10: v1(6727.89,4750) 6767.72,4750 6812.72,4705 6813.62,4705 R198.2@6813.62,4684 6813.62,4635.04 6813.58,4635
NetC131_1: C131.1 R200.2 U33.3 | length 151.5
  Bottom Layer w10: U33.3@7118.23,4472.6 U33.3@7119.8,4472.6 ; C131.1@7128.58,4411 7128.58,4463.82 U33.3@7119.8,4472.6 ; R200.2@7201.38,4480 7193.98,4472.6 U33.3@7119.8,4472.6
NetC132_1: C132.1 R203.1 U33.4 | length 173.9
  Bottom Layer w10: R203.1@6941.38,4343 C132.1@6941.42,4411 C132.1@6941.42,4411 6942.37,4411 6995.19,4463.82 7012.99,4463.82 U33.4@7021.77,4472.6
NetC132_2: C132.2 R203.2 R206.1 U33.1 | length 614
  Bottom Layer w10: R206.1@6756.38,4139 6757.28,4139 6770.24,4151.96 6770.24,4152.86 6845,4227.62 6845,4255.31 6870.62,4280.92 6935.64,4280.92 6997.72,4343 R203.2@6998.62,4343 C132.2@6998.58,4411 C132.2@6998.58,4411 6999.53,4411 7028.09,4439.56 7040.71,4439.56 7065.87,4464.73 7065.87,4509.62 7094.88,4538.62 7109.45,4538.62 U33.1@7118.23,4547.4
NetC133_2: C133.2 R56.1 R201.1 U34.3 | length 491.2
  Top Layer w10: v1(6546.22,4411.45) 6550.82,4411.45 6557.27,4405 6607.75,4405 6616.24,4396.51 6616.24,4395.48 6624.76,4386.96 6629.76,4386.96 6638.62,4378.09 R56.1@6638.62,4374
  Bottom Layer w10: v1(6546.22,4411.45) 6505,4370.23 6505,4301.15 6505.41,4300.74 6505.41,4239.59 6536.5,4208.5 6562.33,4208.5 U34.3@6568.23,4202.6 ; v1@6548.55,4411.45 6595.97,4411.45 C133.2@6596.42,4411 ; C133.2@6596.38,4415 R201.1@6596.38,4480
NetC138_1: C138.1 R205.2 U35.3 | length 151
  Bottom Layer w10: U35.3@7118.23,4200.6 U35.3@7119.8,4200.6 ; C138.1@7128.58,4139 7128.58,4191.82 U35.3@7119.8,4200.6 ; R205.2@7201.38,4207 7194.98,4200.6 U35.3@7119.8,4200.6
NetC139_1: C139.1 R208.1 U35.4 | length 174.9
  Bottom Layer w10: R208.1@6941.38,4070 C139.1@6941.42,4139 C139.1@6941.42,4139 6942.37,4139 6995.19,4191.82 7012.99,4191.82 U35.4@7021.77,4200.6
NetC139_2: C139.2 R208.2 R209.1 U35.1 | length 538.2
  Bottom Layer w10: R209.1@6756.38,4070 6757.28,4070 6770.24,4057.04 6770.24,4056.14 6785.33,4041.04 6968.76,4041.04 6997.72,4070 R208.2@6998.62,4070 C139.2@6998.58,4139 C139.2@6998.58,4139 6999.53,4139 7028.09,4167.56 7040.71,4167.56 7065.87,4192.73 7065.87,4237.62 7094.88,4266.62 7109.45,4266.62 U35.1@7118.23,4275.4
NetC144_1: C144.1 R211.2 U37.3 | length 152.6
  Bottom Layer w10: C144.1@7128.58,3868 7128.58,3920.82 7119.8,3929.6 7118.23,3929.6 7124.63,3936 R211.2@7201.38,3936
NetC145_1: C145.1 R213.1 U37.4 | length 177.7
  Bottom Layer w10: R213.1@6941.38,3800 6946.04,3804.67 6946.04,3863.38 C145.1@6941.42,3868 6942.37,3868 6992.56,3918.18 7010.36,3918.18 U37.4@7021.77,3929.6
NetC145_2: C145.2 R63.1 R213.2 U37.1 | length 767.6
  Top Layer w10: v1(6715,4040) 6759.38,4040 R63.1@6761.38,4042
  Bottom Layer w10: v1(6715,4040) 6818.11,3936.89 6818.11,3870.9 6919.01,3770 6967.72,3770 6997.72,3800 R213.2@6998.62,3800 C145.2@6998.58,3868 C145.2@6998.58,3868 6999.53,3868 7028.09,3896.56 7045.75,3896.56 7047.05,3897.86 7047.86,3897.86 7065.87,3915.87 7065.87,3966.62 7094.88,3995.62 7109.45,3995.62 U37.1@7118.23,4004.4
NetC148_1: C148.1 R223.1 R226.1 R227.2 R228.2 | length 523.9
  Bottom Layer w10: R226.1@7258.62,3330 R223.1@7258.62,3398 ; C148.1@7260,3465 7258.62,3463.62 R223.1@7258.62,3398 ; R227.2@7596.38,3290 R228.2@7538.62,3290 7537.72,3290 7498.67,3329.04 7440.96,3329.04 7365,3405 7265.62,3405 R223.1@7258.62,3398
NetC149_1: C149.1 R229.1 R233.2 R235.1 R236.2 | length 514.1
  Bottom Layer w10: R229.1@7258.62,3262 7259.53,3262 7272.48,3249.04 7272.48,3241.11 7290.1,3223.5 7323.5,3223.5 7325,3225 7356.96,3193.04 7498.58,3193.04 7537.63,3154 C149.1@7538.58,3154 R233.2@7596.38,3154 R235.1@7596.38,3086 R236.2@7538.62,3086
NetC165_2: C165.2 R252.2 R264.2 U41.3 | length 581.6
  Top Layer w10: v1(7675,990) 7675,1019.69 7735,1079.69 v1(7735,1145)
  Bottom Layer w10: U41.3@7437.4,938.23 7437.4,929.37 7446.82,919.96 7488.42,919.96 R264.2@7501.38,907 7502.28,907 7560.44,965.16 7660.16,965.16 7660.16,970.56 7675,985.4 v1(7675,990) ; v1(7735,1145) 7770.38,1145 R252.2@7771.38,1146 C165.2@7771.42,1215 C165.2@7771.42,1215
NetC166_1: C166.1 R247.2 R250.2 R253.1 | length 285.6
  Bottom Layer w10: C166.1@6988.58,1194 R247.2@6988.62,1263 7038.76,1262.96 7107.72,1194 R250.2@7108.62,1194 R253.1@7108.62,1126
NetC167_1: C167.1 R136.1 R249.1 U39.5 | length 472.3
  Top Layer w10: R136.1@7198.62,1432 7233,1432 7270,1395 7270,1343.99 7270.39,1343.6 7270.39,1281.7 7270,1281.31 v1(7270,1243.34)
  Bottom Layer w10: v1(7270,1243.34) 7228.58,1201.92 C167.1@7228.58,1126 7230.38,1127.8 7323.04,1127.8 U39.5@7325.83,1130.59
NetC168_2: C168.2 R255.2 | length 68
  Bottom Layer w10: C168.2@6126.42,1038 C168.2@6126.42,1038 R255.2@6126.38,1106
NetC169_1: C169.1 R258.2 R261.1 U39.2 U39.4 | length 712.5
  Bottom Layer w10: U39.2@7325.83,1053.82 7285.39,1053.82 7260.61,1029.04 7211.42,1029.04 7160.61,978.24 7160.61,961.33 7114.28,915 7085,915 7070.52,929.48 7070.52,956.77 7087.21,973.46 7091.18,973.46 7107.72,990 R261.1@7108.62,990 R258.2@7108.62,1058 7109.53,1058 7139.51,1087.98 7262.98,1087.98 7280,1105 U39.4@7325.83,1105
NetC171_1: C171.1 U29.10 | length 127.1
  Top Layer w8: 6255.76,839.84 U29.10@6285.77,839.84
  Top Layer w10: v1(6223.84,871.76) 6255.76,839.84
  Bottom Layer w10: C171.1@6183.58,900 6184.53,900 6209.51,875.02 6220.59,875.02 v1(6223.84,871.76)
NetC174_1: C174.1 R266.2 R267.2 U41.4 | length 317.6
  Bottom Layer w10: R266.2@7222,836.38 7289.09,836.38 7320.47,805 7400.63,805 7419.76,824.13 7428.62,824.13 7437.4,832.91 U41.4@7437.4,841.77 7498.61,841.77 R267.2@7501.38,839 R267.2@7498.8,836.42
NetC174_2: C174.2 R60.1 R266.1 U41.1 | length 3750.1
  Top Layer w10: R60.1@7238.62,4236 7251.58,4223.04 7257.26,4223.04 7295.38,4184.92 7333.5,4146.81 7333.5,4113.5 7298,4078 7298,3707.36 7383.5,3621.86 7383.5,3079.64 7353.5,3049.64 7353.5,2860.71 7350,2857.21 7350,2668.28 7445,2573.28 7445,1460 7318.5,1333.5 7318.5,1219.91 7290.09,1191.5 7275.18,1191.5 7250,1166.32 7250,977.14 v1(7288.42,938.72)
  Bottom Layer w10: R266.1@7222,893.62 C174.2@7290,893.58 C174.2@7290,893.58 7290,894.53 C174.2@7295.25,899.78 ; v1(7288.42,938.72) 7288.42,906.62 C174.2@7295.25,899.78 ; U41.1@7362.6,938.23 7333.7,938.23 C174.2@7295.25,899.78
NetC177_1: C177.1 R270.2 R271.2 U42.4 | length 440.5
  Bottom Layer w10: R270.2@7222,716.38 C177.1@7290,716.42 C177.1@7290,716.42 7300,706.42 7300,650 7355,595 7415.31,595 7437.4,617.1 U42.4@7437.4,673.54 7471.02,673.54 7500.47,703 R271.2@7501.38,703
NetC177_2: C177.2 R62.1 R270.1 U42.1 | length 3735.3
  Top Layer w10: R62.1@7238.62,4100 7239.53,4100 7278,4061.53 7278,3699.07 7363.5,3613.57 7363.5,3087.92 7333.5,3057.92 7333.5,2869 7330,2865.5 7330,2660 7420,2570 7420,1480 7298.5,1358.5 7298.5,1228.19 7281.81,1211.5 7266.9,1211.5 7230,1174.6 7230,957.63 7249.75,937.88 v1(7249.75,937.08)
  Bottom Layer w10: v1(7249.75,937.08) 7227.08,937.08 7225,935 7211.01,935 7180,903.99 7180,816.53 7222,774.53 R270.1@7222,773.62 R270.1@7222,773.62 C177.2@7290,773.58 7293.58,770 U42.1@7362.6,770
NetC181_2: C181.2 R268.2 R272.2 U42.3 | length 930.9
  Top Layer w10: v1(7395,623.5) 7395,598.78 7449.52,544.26 7500.79,492.99 7531.81,492.99 7533.81,495 7588.59,495 7672.09,578.5 7716.81,578.5 7730.31,565 v1(7870,565)
  Bottom Layer w10: v1(7395,623.5) 7395,696.67 7430.69,732.36 7430.69,763.29 U42.3@7437.4,770 7500.38,770 R268.2@7501.38,771 ; R272.2@7828.62,652 R272.2@7828.62,652 C181.2@7828.58,583 7842.44,569.14 7861.26,569.14 7865.4,565 v1(7870,565)
NetC185_1: C185.1 R273.2
NetC194_1: C194.1 R274.2
NetD1_2: D1.2 R221.1 | length 590.3
  Top Layer w10: D1.2@7476.34,3018 7485,3026.66 7485,3245 7670,3430 v1(7710,3430)
  Bottom Layer w10: R221.1@7653.62,3426 7657.62,3430 v1(7710,3430)
NetD2_2: D2.2 R224.1 | length 630.9
  Top Layer w10: D2.2@7461.34,2930 7510,2978.66 7510,2988.86 7510.96,2989.82 7510.96,3046.18 7510,3047.14 7510,3238.08 7636.92,3365 v1(7705,3365)
  Bottom Layer w10: R224.1@7653.62,3358 7693.4,3358 7700.4,3365 v1(7705,3365)
NetD3_2: D3.2 R230.1 | length 584
  Top Layer w10: D3.2@7461.34,2848 7530.96,2917.62 7530.96,3155.96 7610,3235 7676.81,3235 7686.11,3244.29 v1(7690.71,3244.29)
  Bottom Layer w10: R230.1@7653.62,3222 7666.58,3234.96 7676.77,3234.96 7686.81,3245 v1@7695,3245
NetD4_2: D4.2 R245.2 | length 143.9
  Top Layer w10: D4.2@6685,1425 6691.34,1425 6721.75,1455.41 6721.75,1476.75 v1(6725,1480)
  Bottom Layer w10: R245.2@6704.1,1420 6725,1440.9 v1(6725,1480)
NetD5_2: D5.2 R246.2 | length 224.6
  Top Layer w10: v1@6538.25,1333.25 v1(6535,1330) 6564.62,1300.38 6651.72,1300.38 D5.2@6686.34,1335
  Bottom Layer w10: v1(6535,1330) 6570,1330 R246.2@6575,1325
NetD6_2: D6.2 R251.1 R256.1 | length 283.5
  Top Layer w25: D6.2@6690,1255 6690,1246.34 6726.34,1210 6730,1210 6730,1125.54 6715,1110.54 v1(6715,1110)
  Bottom Layer w25: R256.1@6673.62,1087 6679.08,1092.46 6697.46,1092.46 v1(6715,1110) 6714.62,1110.38 6714.62,1114.91 6674.53,1155 R251.1@6673.62,1155
NetD7_2: D7.2 R260.2 R263.2 | length 297.7
  Top Layer w25: D7.2@6686.34,1170 6679,1162.66 6679,1051.12 6715,1015.12 v1(6715,1015)
  Bottom Layer w25: R263.2@6673.62,951 6679.08,956.46 6679.98,956.46 6715,991.47 v1(6715,1015) 6712.12,1017.88 6674.74,1017.88 R260.2@6673.62,1019
NetD11_2: D11.2 R78.2 | length 149.9
  Top Layer w25: v1(6170,3630) 6170.38,3629.62 6212.95,3629.62 6230,3612.57 R78.2@6230,3610
  Bottom Layer w25: D11.2@6145.67,3700 6162.7,3682.97 6162.7,3637.84 6170,3630.54 v1(6170,3630)
NetD12_2: D12.2 R77.2 | length 315.8
  Top Layer w25: R77.2@890,3610 v1(940,3610)
  Bottom Layer w25: D12.2@712.6,3700 712.6,3698.03 800.63,3610 v1(940,3610)
NetD13_2: D13.2 J10.1 Q3.3
NetD14_2: D14.2 J11.1 Q4.3
NetD15_2: D15.2 R116.2 | length 348.9
  Top Layer w25: v1(6200,2300) 6200.38,2300.38 6270.36,2300.38 6285,2315.03 6285,2431.28 6270.36,2445.92 6245.26,2445.92 6240,2451.18 R116.2@6240,2485
  Bottom Layer w25: D15.2@6145.67,2300 v1(6200,2300)
NetD16_2: D16.2 R118.2 | length 138.7
  Top Layer w25: v1(710,2355) 710.54,2355 721.46,2365.92 754.74,2365.92 765,2376.18 R118.2@765,2395
  Bottom Layer w25: v1(710,2355) 710.38,2354.62 710.38,2302.22 D16.2@712.6,2300
NetD17_2: D17.2 J12.2 Q5.4 | length 140
  Bottom Layer w50: Q5.4@7615,2315.24 7755,2315.24
NetD18_2: D18.2 J16.2 Q6.4 | length 140.2
  Bottom Layer w8: 7755,1700 7755,1700.24
  Bottom Layer w50: Q6.4@7615,1700.24 7755,1700.24
NetHS1_3: HS1.3 R133.2 R134.2
NetJ9_3: J9.3 R48.1 | length 1595.6
  Top Layer w10: R48.1@7238.62,4720 7280,4720 7333.5,4666.5 7333.5,4453.22 7395,4391.72 7395,3730 7549.96,3575.04 7796.56,3575.04 7821.6,3550 J9.3@7837,3550
NetJ9_4: J9.4 R47.1 | length 2260.4
  Top Layer w10: R47.1@6819.51,4715 6918.74,4715 6981.06,4777.32 7017.14,4777.32 7064.82,4825 7300,4825 7353.7,4771.3 7353.7,4545.4 7355,4544.1 7355,4460 7415,4400 7415,3738.28 7554.82,3598.46 7888.54,3598.46 J9.4@7937,3550
NetJ9_5: J9.5 R79.1 | length 678.5
  Top Layer w10: R79.1@7239.53,3616 7240.53,3615 v1(7280,3615) ; J9.5@7827.68,3450 J9.5@7837,3450
  Bottom Layer w10: v1(7280,3615) 7331.63,3563.37 7331.63,3558.37 7380,3510 7777,3510 J9.5@7837,3450
NetJ9_6: J9.6 R84.1 | length 857
  Top Layer w10: R84.1@7238.62,3480 7239.53,3480 7283.87,3524.34 7283.87,3566.86 v1(7280.61,3570.11)
  Bottom Layer w10: v1(7280.61,3570.11) 7285.21,3570.11 7295.32,3560 7301.72,3560 7371.72,3490 7725,3490 7813.46,3401.54 7888.54,3401.54 J9.6@7937,3450
NetJ9_7: J9.7 R227.1 | length 208.3
  Bottom Layer w10: R227.1@7653.62,3290 7755,3290 7804.11,3339.11 7826.11,3339.11 J9.7@7837,3350 J9.7@7836.95,3350.05
NetJ9_8: J9.8 R233.1 | length 364.6
  Bottom Layer w10: R233.1@7653.62,3154 7654.53,3154 7798.99,3298.46 7885.46,3298.46 J9.8@7937,3350
NetJ9_9: J9.9 R232.1 | length 760.9
  Bottom Layer w10: R232.1@7258.62,3194 7259.53,3194 7272.48,3181.04 7272.48,3180.14 7286.12,3166.5 7348.81,3166.5 7438.5,3076.81 7438.5,3076.51 7462.71,3052.3 7692.6,3052.3 7768.19,3127.88 7768.19,3198.19 7804.23,3234.23 7805.83,3234.23 7821.6,3250 J9.9@7837,3250
NetJ9_10: J9.10 R237.1 | length 811.8
  Bottom Layer w10: R237.1@7258.62,3058 7259.53,3058 7272.48,3045.04 7272.48,3044.14 7286.62,3030 7700,3030 7788.54,3118.54 7788.54,3170.07 7816.93,3198.46 7885.46,3198.46 J9.10@7937,3250
NetQ1_3: Q1.3 R140.1 | length 88.5
  Top Layer w10: Q1.3@7091.34,1120 Q1.3@7089.37,1120 7100.12,1130.75 7112.22,1130.75 7140.47,1159 R140.1@7141.38,1159 R140.1@7128.42,1146.04
NetQ3_1: Q3.1 R241.2 | length 146.3
  Bottom Layer w10: Q3.1@7610,2875 7618.15,2866.85 7634.87,2866.85 7717.72,2784 R241.2@7718.62,2784
NetQ4_1: Q4.1 R242.2 | length 211.8
  Bottom Layer w10: Q4.1@7610.63,2547.6 7612.6,2547.6 7623.35,2558.35 7623.35,2560.31 7640,2576.97 7640,2638.28 7715,2713.28 R242.2@7715,2715
NetQ5_1: Q5.1 R243.2 | length 380.6
  Bottom Layer w10: R243.2@7410,1910.9 7417.92,1910.9 7458.82,1870 7630,1870 7665,1905 7665.94,1905 7710,1949.06 Q5.1@7710,1980
NetQ6_1: Q6.1 R244.2 | length 396.7
  Bottom Layer w10: R244.2@7410,1355.9 7417.92,1355.9 7458.82,1315 7675,1315 7705,1345 ; 7703.89,1345 7703.89,1415.51 Q6.1@7705.16,1416.77
NetQ7_4: Q7.4 Q8.4 R153.2 U30.10 | length 503.8
  Top Layer w10: v1(6756.95,788.05) 6780,765 6780,586.36 ; v1(6785,572) 6819.38,572 R153.2@6821.38,570 6821.75,570 6834.7,557.04 6834.7,545.3 6856.34,523.66 6883.41,523.66 6917.7,489.37 U30.10@6931.5,489.37
  Bottom Layer w10: v1(6756.95,788.05) 6758.47,786.53 6810.32,786.53 Q7.4@6811.3,787.5 ; v1(6785,572) 6785,567.4 6790.55,561.85 6790.55,542.01 6797.56,535 Q8.4@6804.88,535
